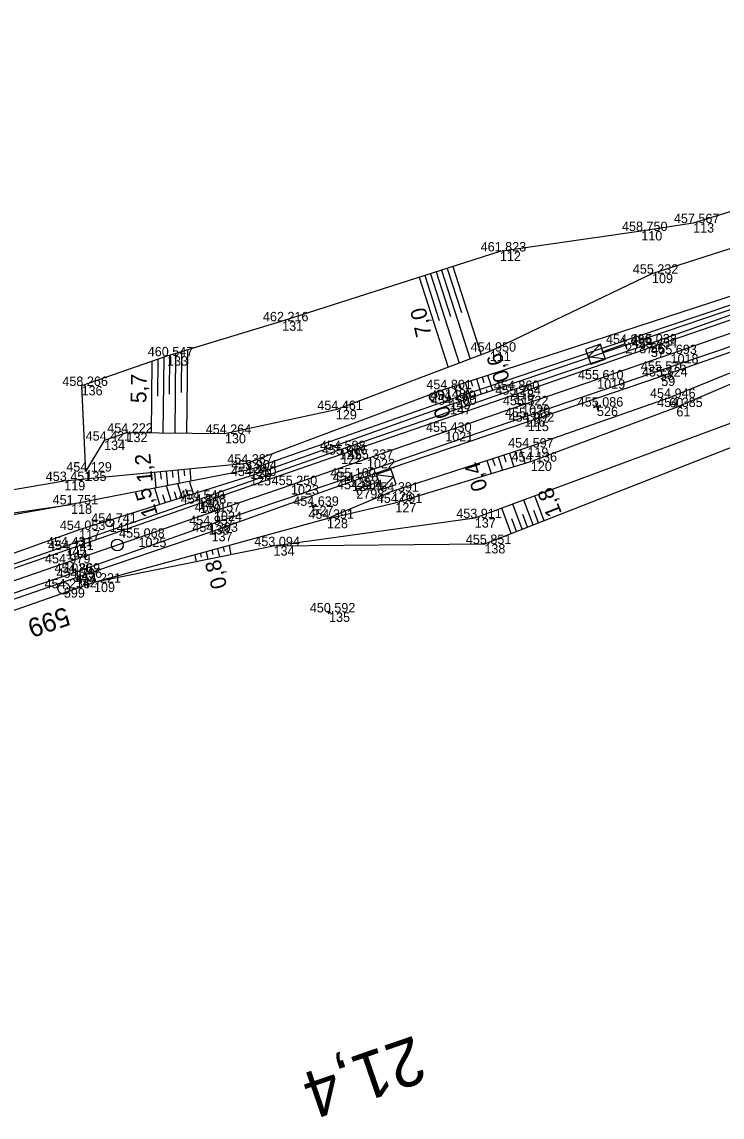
# Model space of a CAD drawing. Extents: x -751615 to -750797, y -1114905 to -1114561.
# Drawn here: x -751025.5 to -750936.3, y -1114715.7 to -1114576.3 of the extents above; entities that cross this region are included whole.
import ezdxf

# ---------------------------------------------------------------- set-up
doc = ezdxf.new("R2010")
doc.units = 0
for name, color, linetype in [('Vrstva 1', 7, 'Continuous'), ('Vrstva 4', 7, 'Continuous'), ('Vrstva 48', 7, 'Continuous'), ('Vrstva 49', 7, 'Continuous'), ('Vrstva 60', 7, 'Continuous'), ('Vrstva 61', 7, 'Continuous'), ('Vrstva 63', 7, 'Continuous'), ('Vrstva 7', 7, 'Continuous'), ('Vrstva 8', 7, 'Continuous')]:
    doc.layers.add(name, color=color, linetype=linetype)

msp = doc.modelspace()

# ---------------------------------------------------------------- linework, layer by layer
at = {"layer": 'Vrstva 1'}
msp.add_lwpolyline([(-750820.34, -1114576.33), (-750829.58, -1114579.52), (-750838.84, -1114582.71), (-750848.38, -1114586.01), (-750858.08, -1114589.35), (-750867.34, -1114592.54), (-750876.53, -1114595.72), (-750885.99, -1114598.98), (-750895.39, -1114602.23), (-750902.99, -1114604.84), (-750908.21, -1114606.65), (-750914.74, -1114608.9), (-750924.08, -1114612.11), (-750933.49, -1114615.37), (-750942.9, -1114618.61), (-750952.24, -1114621.83), (-750961.8, -1114625.13), (-750971.59, -1114628.51), (-750981.56, -1114631.95), (-750991.25, -1114635.29), (-751001.05, -1114638.67), (-751010.67, -1114641.99), (-751020.12, -1114645.25), (-751029.87, -1114648.61)], dxfattribs=at)
at = {"layer": 'Vrstva 4'}
for points in [[(-750909.85, -1114605.66), (-750913.63, -1114606.28), (-750928.94, -1114611.39), (-750945.45, -1114617.26), (-750962.95, -1114623.18), (-750985.09, -1114630.83), (-751003.05, -1114637.15), (-751019.96, -1114643.08), (-751037.54, -1114649.18), (-751047.43, -1114652.08)], [(-750909.85, -1114605.66), (-750913.48, -1114606.81), (-750928.75, -1114612.04), (-750945.4, -1114617.79), (-750962.77, -1114623.79), (-750984.85, -1114631.4), (-751002.84, -1114637.65), (-751019.82, -1114643.56), (-751037.45, -1114649.67)], [(-750908.4, -1114608.25), (-750913.16, -1114610.92), (-750927.28, -1114615.56), (-750944.08, -1114621.47), (-750961.07, -1114627.22), (-750983.47, -1114634.85), (-751001.35, -1114641.24), (-751018.65, -1114647.09), (-751035.57, -1114652.97), (-751044.4, -1114656.03)], [(-750908.4, -1114608.25), (-750913.03, -1114609.92), (-750927.56, -1114615.04), (-750944.23, -1114620.72), (-750961.52, -1114626.65), (-750983.78, -1114634.33), (-751001.73, -1114640.38), (-751018.89, -1114646.44), (-751036.64, -1114652.47)]]:
    msp.add_lwpolyline(points, dxfattribs=at)
at = {"layer": 'Vrstva 48'}
for p, q in [((-750972.76, -1114608.16), (-750970.94, -1114613.83)), ((-750972.05, -1114607.93), (-750968.42, -1114619.24)), ((-750971.33, -1114607.7), (-750969.52, -1114613.34)), ((-750970.62, -1114607.47), (-750967.02, -1114618.71)), ((-750974.9, -1114608.84), (-750971.23, -1114620.31)), ((-750974.19, -1114608.61), (-750972.36, -1114614.33)), ((-750973.47, -1114608.38), (-750969.83, -1114619.77)), ((-751008.19, -1114619.29), (-751008.25, -1114623.98)), ((-751007.44, -1114619.03), (-751007.55, -1114628.68)), ((-751006.69, -1114618.78), (-751006.74, -1114623.73)), ((-751005.93, -1114618.55), (-751006.05, -1114628.69)), ((-751005.18, -1114618.33), (-751005.24, -1114623.51)), ((-751004.43, -1114618.1), (-751004.55, -1114628.71)), ((-751008.94, -1114619.55), (-751009.05, -1114628.66)), ((-750969.04, -1114622.23), (-750968.59, -1114623.61)), ((-750968.33, -1114622), (-750968.11, -1114622.69)), ((-750967.62, -1114621.77), (-750967.17, -1114623.13)), ((-750966.9, -1114621.54), (-750966.68, -1114622.22)), ((-750966.19, -1114621.3), (-750965.75, -1114622.65)), ((-750970.47, -1114622.7), (-750970.02, -1114624.09)), ((-750969.76, -1114622.47), (-750969.53, -1114623.16)), ((-750968.39, -1114624.2), (-750968.59, -1114623.61)), ((-750967.68, -1114623.96), (-750967.78, -1114623.66)), ((-750966.97, -1114623.71), (-750967.17, -1114623.13)), ((-750966.26, -1114623.47), (-750966.35, -1114623.18)), ((-750965.55, -1114623.23), (-750965.74, -1114622.65)), ((-750969.81, -1114624.68), (-750970.01, -1114624.09)), ((-750969.1, -1114624.44), (-750969.2, -1114624.14)), ((-750965.56, -1114631.95), (-750965.29, -1114632.78)), ((-750964.85, -1114631.71), (-750964.3, -1114633.39)), ((-750964.14, -1114631.48), (-750963.86, -1114632.33)), ((-750963.42, -1114631.25), (-750962.87, -1114632.95)), ((-750962.71, -1114631.02), (-750962.43, -1114631.88)), ((-750962, -1114630.79), (-750961.43, -1114632.52)), ((-751005.64, -1114633.39), (-751005.48, -1114635.07)), ((-751004.89, -1114633.32), (-751004.81, -1114634.12)), ((-751004.14, -1114633.25), (-751004, -1114634.78)), ((-750966.28, -1114632.18), (-750965.74, -1114633.83)), ((-751008.62, -1114633.67), (-751008.44, -1114635.64)), ((-751007.88, -1114633.6), (-751007.79, -1114634.55)), ((-751007.13, -1114633.53), (-751006.96, -1114635.35)), ((-751006.38, -1114633.46), (-751006.3, -1114634.33)), ((-751003.65, -1114636.4), (-751004.15, -1114634.81)), ((-751007.94, -1114637.76), (-751008.59, -1114635.67)), ((-751006.51, -1114637.3), (-751007.11, -1114635.38)), ((-751005.79, -1114637.08), (-751006.08, -1114636.16)), ((-751005.08, -1114636.85), (-751005.63, -1114635.1)), ((-751004.36, -1114636.63), (-751004.62, -1114635.79)), ((-751007.22, -1114637.53), (-751007.54, -1114636.53)), ((-750960.41, -1114640.36), (-750961.58, -1114637.19)), ((-750959.01, -1114639.82), (-750960.18, -1114636.67)), ((-750963.2, -1114641.46), (-750964.4, -1114638.23)), ((-750961.8, -1114640.91), (-750962.99, -1114637.71)), ((-750959.71, -1114640.09), (-750960.29, -1114638.51)), ((-750962.5, -1114641.18), (-750963.1, -1114639.58)), ((-750961.1, -1114640.64), (-750961.7, -1114639.04)), ((-750999.13, -1114643), (-750998.89, -1114644.17)), ((-751003.48, -1114644.19), (-751003.3, -1114645.07)), ((-751002.76, -1114643.99), (-751002.66, -1114644.45)), ((-751002.03, -1114643.79), (-751001.83, -1114644.77)), ((-751001.31, -1114643.59), (-751001.2, -1114644.11)), ((-751000.58, -1114643.39), (-751000.36, -1114644.47)), ((-750999.86, -1114643.19), (-750999.74, -1114643.76))]:
    msp.add_line(p, q, dxfattribs=at)
at = {"layer": 'Vrstva 49'}
for p, q in [((-750996.9, -1114632.56), (-750996.4, -1114633.3)), ((-751058.95, -1114643.47), (-751019.25, -1114637.75)), ((-750967.83, -1114639.5), (-750993.46, -1114643.07)), ((-750993.46, -1114643.07), (-751016.33, -1114647.71)), ((-750966.61, -1114642.79), (-750993.46, -1114643.07)), ((-750986.17, -1114651.61), (-750986.62, -1114651.39)), ((-750986.28, -1114651.28), (-750986.5, -1114651.73))]:
    msp.add_line(p, q, dxfattribs=at)
for points in [[(-750914.28, -1114599.04), (-750918.73, -1114597.89), (-750932.03, -1114599.47), (-750940.02, -1114601.94), (-750946.63, -1114602.95), (-750964.63, -1114605.55), (-750992.36, -1114614.44), (-751007.03, -1114618.89), (-751017.91, -1114622.67), (-751017.41, -1114633.57)], [(-750914.28, -1114599.04), (-750918.79, -1114599.93), (-750945.26, -1114608.38), (-750965.92, -1114618.3), (-750985.53, -1114625.73), (-750999.65, -1114628.77), (-751012.19, -1114628.62), (-751015.04, -1114629.63), (-751017.41, -1114633.57)], [(-750971.64, -1114623.08), (-750922.66, -1114607.14), (-750911.92, -1114603.43)], [(-750912.49, -1114604.31), (-750923.14, -1114608.3), (-750971.05, -1114624.44)], [(-750911.85, -1114604.92), (-750922.68, -1114608.69), (-750970.96, -1114625.07)], [(-750907.43, -1114611.53), (-750909.43, -1114611.74), (-750926.28, -1114617.37), (-750943.06, -1114624.19), (-750961.13, -1114630.51), (-750978.4, -1114636.12), (-750986.66, -1114639.58), (-751016.33, -1114647.71)], [(-750986.66, -1114639.58), (-750977.95, -1114637.56), (-750960.69, -1114632.29), (-750942.15, -1114625.35), (-750926.02, -1114618.44), (-750909.2, -1114613.04), (-750906.79, -1114617.51)], [(-750906.79, -1114617.51), (-750919.4, -1114621.54), (-750967.83, -1114639.5)], [(-750904.52, -1114618.56), (-750918.92, -1114624.13), (-750966.61, -1114642.79)], [(-750971.64, -1114623.08), (-750996.9, -1114632.56), (-751020.12, -1114634.77)], [(-750971.05, -1114624.44), (-750996.4, -1114633.3), (-751019.25, -1114637.75)], [(-750970.96, -1114625.07), (-750996.45, -1114634.14), (-751018.23, -1114641), (-751047.34, -1114651.41), (-751047.65, -1114652.4)], [(-751020.12, -1114634.77), (-751060.04, -1114641.62), (-751070.13, -1114648.35), (-751076.53, -1114658.31), (-751078.11, -1114663.72)], [(-751019.25, -1114637.75), (-751058.49, -1114644.76), (-751068.92, -1114649.96), (-751075.46, -1114658.88), (-751078.11, -1114663.72)], [(-751016.33, -1114647.71), (-751044.62, -1114657.57), (-751046.05, -1114656.65)]]:
    msp.add_lwpolyline(points, dxfattribs=at)
at = {"layer": 'Vrstva 60'}
for p, q in [((-750940.02, -1114601.94), (-750940.02, -1114601.94)), ((-750946.63, -1114602.95), (-750946.63, -1114602.95)), ((-750964.63, -1114605.55), (-750964.63, -1114605.55)), ((-750945.26, -1114608.38), (-750945.26, -1114608.38)), ((-750992.36, -1114614.44), (-750992.36, -1114614.44)), ((-750948.67, -1114617.31), (-750948.67, -1114617.31)), ((-750945.45, -1114617.26), (-750945.45, -1114617.26)), ((-750945.4, -1114617.79), (-750945.4, -1114617.79)), ((-751007.03, -1114618.89), (-751007.03, -1114618.89)), ((-750965.92, -1114618.3), (-750965.92, -1114618.3)), ((-750942.9, -1114618.61), (-750942.9, -1114618.61)), ((-750944.23, -1114620.72), (-750944.23, -1114620.72)), ((-750952.24, -1114621.83), (-750952.24, -1114621.83)), ((-750944.08, -1114621.47), (-750944.08, -1114621.47)), ((-751017.91, -1114622.67), (-751017.91, -1114622.67)), ((-750971.64, -1114623.08), (-750971.64, -1114623.08)), ((-750962.95, -1114623.18), (-750962.95, -1114623.18)), ((-750971.05, -1114624.44), (-750971.05, -1114624.44)), ((-750962.77, -1114623.79), (-750962.77, -1114623.79)), ((-750943.06, -1114624.19), (-750943.06, -1114624.19)), ((-750985.53, -1114625.73), (-750985.53, -1114625.73)), ((-750970.96, -1114625.07), (-750970.96, -1114625.07)), ((-750961.8, -1114625.13), (-750961.8, -1114625.13)), ((-750952.27, -1114625.3), (-750952.27, -1114625.3)), ((-750942.15, -1114625.35), (-750942.15, -1114625.35)), ((-750961.52, -1114626.65), (-750961.52, -1114626.65)), ((-750961.07, -1114627.22), (-750961.07, -1114627.22)), ((-751012.19, -1114628.62), (-751012.19, -1114628.62)), ((-750999.65, -1114628.77), (-750999.65, -1114628.77)), ((-750971.59, -1114628.51), (-750971.59, -1114628.51)), ((-751015.04, -1114629.63), (-751015.04, -1114629.63)), ((-750961.13, -1114630.51), (-750961.13, -1114630.51)), ((-750985.09, -1114630.83), (-750985.09, -1114630.83)), ((-750984.85, -1114631.4), (-750984.85, -1114631.4)), ((-750981.56, -1114631.95), (-750981.56, -1114631.95)), ((-750996.9, -1114632.56), (-750996.9, -1114632.56)), ((-750996.4, -1114633.3), (-750996.4, -1114633.3)), ((-750960.69, -1114632.29), (-750960.69, -1114632.29)), ((-751020.12, -1114634.77), (-751020.12, -1114634.77)), ((-751017.41, -1114633.57), (-751017.41, -1114633.57)), ((-750996.45, -1114634.14), (-750996.45, -1114634.14)), ((-750983.78, -1114634.33), (-750983.78, -1114634.33)), ((-750991.25, -1114635.29), (-750991.25, -1114635.29)), ((-750983.47, -1114634.85), (-750983.47, -1114634.85)), ((-750982.92, -1114635.82), (-750982.92, -1114635.82)), ((-750978.4, -1114636.12), (-750978.4, -1114636.12)), ((-751003.05, -1114637.15), (-751003.05, -1114637.15)), ((-750977.95, -1114637.56), (-750977.95, -1114637.56)), ((-751019.25, -1114637.75), (-751019.25, -1114637.75)), ((-751002.84, -1114637.65), (-751002.84, -1114637.65)), ((-751001.05, -1114638.67), (-751001.05, -1114638.67)), ((-750988.5, -1114637.93), (-750988.5, -1114637.93)), ((-751014.32, -1114640.08), (-751014.32, -1114640.08)), ((-751001.73, -1114640.38), (-751001.73, -1114640.38)), ((-750986.66, -1114639.58), (-750986.66, -1114639.58)), ((-750967.83, -1114639.5), (-750967.83, -1114639.5)), ((-751018.23, -1114641), (-751018.23, -1114641)), ((-751001.35, -1114641.24), (-751001.35, -1114641.24)), ((-751019.96, -1114643.08), (-751019.96, -1114643.08)), ((-751010.67, -1114641.99), (-751010.67, -1114641.99)), ((-750993.46, -1114643.07), (-750993.46, -1114643.07)), ((-750966.61, -1114642.79), (-750966.61, -1114642.79)), ((-751019.82, -1114643.56), (-751019.82, -1114643.56)), ((-751020.12, -1114645.25), (-751020.12, -1114645.25)), ((-751018.89, -1114646.44), (-751018.89, -1114646.44)), ((-751018.65, -1114647.09), (-751018.65, -1114647.09)), ((-751020.17, -1114648.43), (-751020.17, -1114648.43)), ((-751016.33, -1114647.71), (-751016.33, -1114647.71)), ((-750986.39, -1114651.5), (-750986.39, -1114651.5))]:
    msp.add_line(p, q, dxfattribs=at)
at = {"layer": 'Vrstva 63'}
msp.add_line((-751020.12, -1114648.41), (-751020.22, -1114648.44), dxfattribs=at)
msp.add_circle((-751020.17, -1114648.43), 0.756, dxfattribs=at)
at = {"layer": 'Vrstva 7'}
for p, q in [((-750952.1, -1114625.78), (-750952.43, -1114624.83)), ((-750951.8, -1114625.14), (-750952.74, -1114625.47)), ((-750988.34, -1114638.4), (-750988.66, -1114637.46)), ((-750988.03, -1114637.77), (-750988.97, -1114638.09)), ((-751014.27, -1114640.06), (-751014.37, -1114640.1))]:
    msp.add_line(p, q, dxfattribs=at)
for centre, radius in [((-751014.32, -1114640.08), 0.5), ((-751013.35, -1114642.91), 0.75)]:
    msp.add_circle(centre, radius, dxfattribs=at)
at = {"layer": 'Vrstva 8'}
for p, q in [((-750948.42, -1114618.02), (-750948.91, -1114616.6)), ((-750983.16, -1114635.1), (-750982.69, -1114636.53))]:
    msp.add_line(p, q, dxfattribs=at)
for points in [[(-750948.67, -1114617.31), (-750951.5, -1114618.31), (-750951.83, -1114617.36), (-750953.71, -1114618.02), (-750953.05, -1114619.91), (-750951.16, -1114619.25), (-750951.5, -1114618.31)], [(-750951.16, -1114619.25), (-750953.38, -1114618.97), (-750951.83, -1114617.36)], [(-750982.92, -1114635.82), (-750980.07, -1114634.88), (-750979.76, -1114635.83), (-750977.86, -1114635.2), (-750978.49, -1114633.3), (-750980.39, -1114633.93), (-750980.07, -1114634.88)], [(-750980.39, -1114633.93), (-750978.17, -1114634.25), (-750979.76, -1114635.83)]]:
    msp.add_lwpolyline(points, dxfattribs=at)

# ---------------------------------------------------------------- texts
at = {"layer": 'Vrstva 48'}
for s, rotation, p in [('7,0', 102.7655, (-750973.31, -1114616.17)), ('0,6', 108.0241, (-750963.34, -1114621.83)), ('5,7', 89.1902, (-751009.66, -1114624.86)), ('0,3', 108.7434, (-750970.79, -1114626.41)), ('1,2', 95.4268, (-751008.82, -1114634.89)), ('0,4', 108.0048, (-750966.16, -1114635.7)), ('1,5', 107.4875, (-751008.17, -1114639.01)), ('1,8', 111.3678, (-750956.7, -1114638.87)), ('0,8', 105.3221, (-750999.34, -1114648.2))]:
    msp.add_text(s, height=2, rotation=rotation, dxfattribs=at).set_placement(p)
at = {"layer": 'Vrstva 60'}
for s, p in [('113', (-750940.02, -1114603.14)), ('110', (-750946.63, -1114604.15)), ('112', (-750964.63, -1114606.75)), ('109', (-750945.26, -1114609.58)), ('131', (-750992.36, -1114615.64)), ('2787', (-750948.67, -1114618.51)), ('56', (-750945.45, -1114618.46)), ('57', (-750945.4, -1114618.99)), ('133', (-751007.03, -1114620.09)), ('111', (-750965.92, -1114619.5)), ('1018', (-750942.9, -1114619.81)), ('58', (-750944.23, -1114621.92)), ('1019', (-750952.24, -1114623.03)), ('59', (-750944.08, -1114622.67)), ('136', (-751017.91, -1114623.87)), ('148', (-750971.64, -1114624.28)), ('118', (-750962.95, -1114624.38)), ('149', (-750971.05, -1114625.64)), ('117', (-750962.77, -1114624.99)), ('60', (-750943.06, -1114625.39)), ('129', (-750985.53, -1114626.93)), ('147', (-750970.96, -1114626.27)), ('1020', (-750961.8, -1114626.33)), ('526', (-750952.27, -1114626.5)), ('61', (-750942.15, -1114626.55)), ('116', (-750961.52, -1114627.85)), ('115', (-750961.07, -1114628.42)), ('132', (-751012.19, -1114629.82)), ('130', (-750999.65, -1114629.97)), ('1021', (-750971.59, -1114629.71)), ('134', (-751015.04, -1114630.83)), ('119', (-750961.13, -1114631.71)), ('121', (-750985.09, -1114632.03)), ('122', (-750984.85, -1114632.59)), ('1022', (-750981.56, -1114633.15)), ('124', (-750996.9, -1114633.76)), ('126', (-750996.4, -1114634.5)), ('120', (-750960.69, -1114633.49)), ('119', (-751020.12, -1114635.97)), ('135', (-751017.41, -1114634.77)), ('125', (-750996.45, -1114635.33)), ('123', (-750983.78, -1114635.53)), ('1023', (-750991.25, -1114636.49)), ('124', (-750983.47, -1114636.05)), ('2798', (-750982.92, -1114637.02)), ('126', (-750978.4, -1114637.32)), ('140', (-751003.05, -1114638.35)), ('127', (-750977.95, -1114638.76)), ('118', (-751019.25, -1114638.95)), ('139', (-751002.84, -1114638.85)), ('1024', (-751001.05, -1114639.86)), ('527', (-750988.5, -1114639.13)), ('141', (-751014.32, -1114641.28)), ('138', (-751001.73, -1114641.58)), ('128', (-750986.66, -1114640.78)), ('137', (-750967.83, -1114640.7)), ('117', (-751018.23, -1114642.2)), ('137', (-751001.35, -1114642.44)), ('145', (-751019.96, -1114644.28)), ('1025', (-751010.67, -1114643.19)), ('134', (-750993.46, -1114644.27)), ('138', (-750966.61, -1114643.99)), ('144', (-751019.82, -1114644.76)), ('1026', (-751020.12, -1114646.45)), ('143', (-751018.89, -1114647.64)), ('142', (-751018.65, -1114648.29)), ('599', (-751020.17, -1114649.62)), ('109', (-751016.33, -1114648.91)), ('135', (-750986.39, -1114652.7))]:
    msp.add_text(s, height=1.2, dxfattribs=at).set_placement(p)
at = {"layer": 'Vrstva 61'}
for s, p in [('457.567', (-750942.47, -1114601.94)), ('458.750', (-750949.08, -1114602.95)), ('461.823', (-750967.08, -1114605.55)), ('455.232', (-750947.7, -1114608.38)), ('462.216', (-750994.81, -1114614.44)), ('454.896', (-750951.12, -1114617.31)), ('455.038', (-750947.9, -1114617.26)), ('455.454', (-750947.85, -1114617.79)), ('460.547', (-751009.48, -1114618.89)), ('454.950', (-750968.37, -1114618.3)), ('455.693', (-750945.35, -1114618.61)), ('455.610', (-750954.69, -1114621.83)), ('455.576', (-750946.68, -1114620.72)), ('455.124', (-750946.53, -1114621.47)), ('458.266', (-751020.36, -1114622.67)), ('454.801', (-750974, -1114623.08)), ('454.860', (-750965.4, -1114623.18)), ('454.249', (-750973.5, -1114624.44)), ('455.254', (-750965.22, -1114623.79)), ('454.946', (-750945.51, -1114624.19)), ('454.461', (-750987.89, -1114625.73)), ('454.500', (-750973.41, -1114625.07)), ('455.522', (-750964.25, -1114625.13)), ('455.086', (-750954.72, -1114625.3)), ('454.385', (-750944.6, -1114625.35)), ('455.375', (-750963.98, -1114626.65)), ('454.992', (-750963.52, -1114627.22)), ('454.222', (-751014.64, -1114628.62)), ('454.264', (-751002.1, -1114628.77)), ('455.430', (-750974.04, -1114628.51)), ('454.421', (-751017.39, -1114629.63)), ('454.598', (-750987.54, -1114630.83)), ('455.066', (-750987.3, -1114631.4)), ('454.597', (-750963.58, -1114630.51)), ('454.387', (-750999.35, -1114632.56)), ('455.337', (-750984.01, -1114631.95)), ('454.136', (-750963.15, -1114632.29)), ('454.129', (-751019.86, -1114633.57)), ('454.350', (-750998.9, -1114634.14)), ('453.904', (-750998.85, -1114633.3)), ('455.100', (-750986.23, -1114634.33)), ('453.451', (-751022.47, -1114634.77)), ('455.250', (-750993.7, -1114635.29)), ('454.726', (-750985.92, -1114634.85)), ('454.604', (-750985.37, -1114635.82)), ('454.540', (-751005.5, -1114637.15)), ('454.391', (-750980.75, -1114636.12)), ('451.751', (-751021.6, -1114637.75)), ('454.848', (-751005.29, -1114637.65)), ('455.157', (-751003.5, -1114638.67)), ('454.639', (-750990.95, -1114637.93)), ('454.091', (-750980.31, -1114637.56)), ('454.741', (-751016.68, -1114640.08)), ('454.391', (-750989.02, -1114639.58)), ('453.911', (-750970.19, -1114639.5)), ('454.053', (-751020.68, -1114641)), ('454.957', (-751004.19, -1114640.38)), ('454.393', (-751003.8, -1114641.24)), ('455.068', (-751013.13, -1114641.99)), ('455.851', (-750968.97, -1114642.79)), ('454.431', (-751022.31, -1114643.08)), ('454.741', (-751022.17, -1114643.56)), ('453.094', (-750995.91, -1114643.07)), ('454.979', (-751022.58, -1114645.25)), ('454.869', (-751021.35, -1114646.44)), ('454.396', (-751021.1, -1114647.09)), ('454.236', (-751022.62, -1114648.43)), ('454.221', (-751018.69, -1114647.71)), ('450.592', (-750988.84, -1114651.5))]:
    msp.add_text(s, height=1.2, dxfattribs=at).set_placement(p)
at = {"layer": 'Vrstva 63'}
msp.add_text('599', height=2.4, rotation=199.0601, dxfattribs=at).set_placement((-751019.93, -1114650.75))
at = {"layer": 'Vrstva 7'}
msp.add_text('21,4', height=6, rotation=199.015, dxfattribs=at).set_placement((-750975.49, -1114705.31))

doc.saveas('drawing.dxf')
